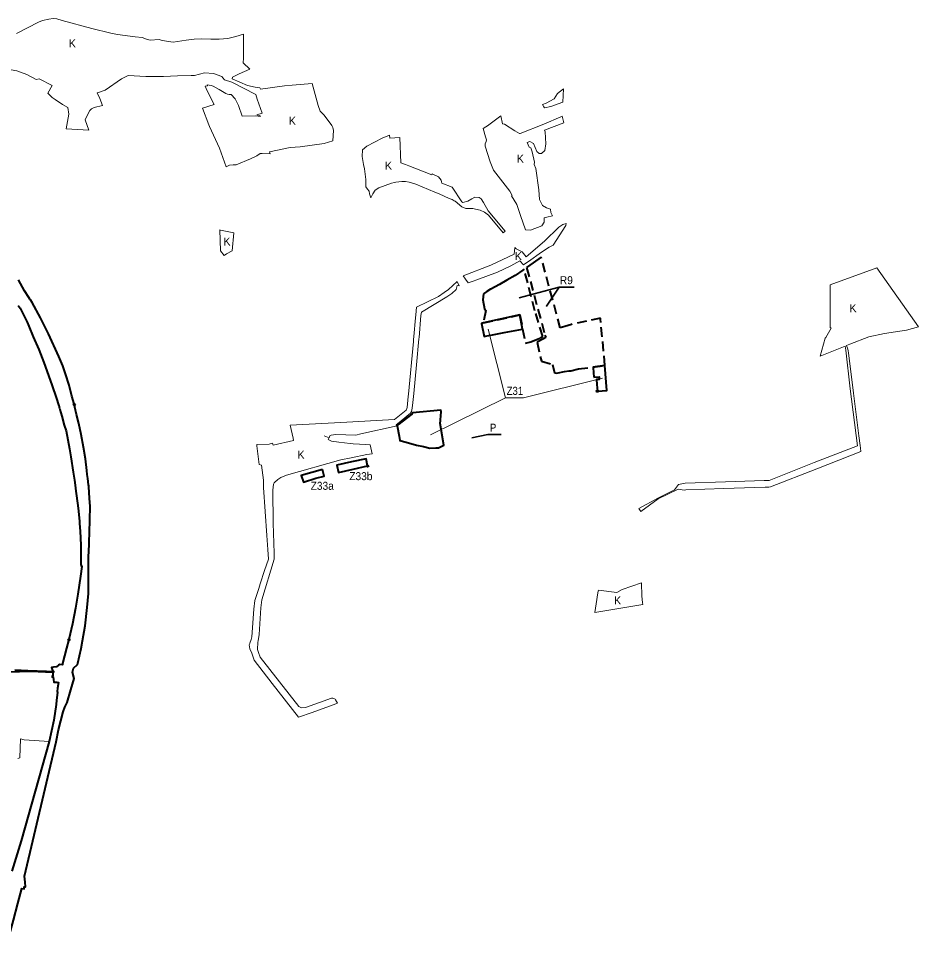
# Model space of a CAD drawing. Extents: x -650276 to -642489, y -1074311 to -1066658.
# Drawn here: x -645184 to -642489, y -1071606 to -1068813 of the extents above; entities that cross this region are included whole.
import ezdxf

# ---------------------------------------------------------------- set-up
doc = ezdxf.new("R2010")
doc.units = 0
doc.header["$LTSCALE"] = 9.6
doc.header["$PDMODE"] = 32
doc.header["$PDSIZE"] = 4.8
doc.linetypes.add('MEDIUM_DASHED', pattern=[4.5, 3, -1.5])
for name, color, linetype, lineweight in [('44', 7, 'Continuous', 40), ('45', 7, 'Continuous', 40), ('46', 7, 'Continuous', 13), ('47', 7, 'Continuous', 13), ('48', 7, 'Continuous', 13), ('60', 7, 'Continuous', 35), ('61', 7, 'MEDIUM_DASHED', 40), ('62', 7, 'Continuous', 35)]:
    doc.layers.add(name, color=color, linetype=linetype, lineweight=lineweight)

msp = doc.modelspace()

# ---------------------------------------------------------------- linework, layer by layer
at = {"layer": '44'}
for points in [[(-645017.46, -1069970.61), (-645018.28, -1069967.49), (-645024.45, -1069944.43), (-645032.85, -1069912.07), (-645043.5, -1069878.37), (-645051.78, -1069854.2), (-645063.26, -1069825.99), (-645095.1, -1069757.62), (-645118.98, -1069710.08), (-645143.56, -1069664.05), (-645148.8, -1069656.1), (-645150.3, -1069653.84), (-645153.33, -1069649.24), (-645166.67, -1069629), (-645184.88, -1069596.58)], [(-645185.17, -1069673.38), (-645179.12, -1069681.3), (-645170.3, -1069698.91), (-645158.43, -1069722.61), (-645153.44, -1069734.71), (-645140.27, -1069766.68), (-645123.84, -1069805.38), (-645108.74, -1069843.58), (-645094.42, -1069882.65), (-645083.31, -1069913.37), (-645071.53, -1069948.89), (-645063.96, -1069973.73), (-645063.23, -1069976.2), (-645062.57, -1069978.46), (-645061.76, -1069981.21), (-645060.612, -1069985.022), (-645054.73, -1070004.56), (-645047.28, -1070031.83), (-645042.27, -1070049.23), (-645032.21, -1070102.73), (-645027.49, -1070126.56), (-645021.14, -1070173.07), (-645018.56, -1070184.92), (-645016.92, -1070196.32), (-645013.77, -1070220.04), (-645013.51, -1070222.04), (-645005.98, -1070280.14), (-645002.308, -1070319.268), (-645001.81, -1070324.58), (-645001.64, -1070326.4)], [(-645010.54, -1069999.3), (-645015.548, -1069978.177), (-645016.01, -1069976.23), (-645016.89, -1069972.82), (-645017.46, -1069970.61)], [(-645166.34, -1071384.07), (-645071.99, -1070980.72), (-645064.39, -1070944.7), (-645050.47, -1070891.48), (-645045.74, -1070877.19), (-645043, -1070871.35), (-645039.25, -1070863.33), (-645028.25, -1070824.83), (-645018.18, -1070791.34), (-645023.25, -1070772.62), (-645019.57, -1070760.07), (-645007.68, -1070749.5), (-645006.739, -1070745.384), (-645001.71, -1070723.39), (-644997.14, -1070700.88), (-644992.6, -1070677.92), (-644985.04, -1070633.43), (-644978.44, -1070578.56), (-644975.05, -1070536.16), (-644974.44, -1070482.48), (-644975.29, -1070440.14), (-644974.69, -1070427.86), (-644972.48, -1070389.15), (-644971.37, -1070345.98), (-644970.61, -1070323.44), (-644970.55, -1070321.56), (-644970.524, -1070315.358), (-644970.36, -1070275.49), (-644971.47, -1070250.14), (-644974, -1070216.2), (-644974.29, -1070213.17), (-644974.49, -1070210.98), (-644976.94, -1070191.41), (-644978.49, -1070180.05), (-644979.57, -1070167.9), (-644984.21, -1070132.81), (-644989.62, -1070097.79), (-644996.88, -1070059.73), (-645004.02, -1070026.44), (-645010.54, -1069999.3)], [(-645001.64, -1070326.4), (-644999.47, -1070349.63), (-644997.87, -1070391.16), (-644998.25, -1070430.5), (-644998.17, -1070450.59), (-644995.14, -1070455.72), (-644998.92, -1070484.58), (-645006.44, -1070538.78), (-645014.07, -1070580.72), (-645022.64, -1070626.93), (-645033.53, -1070674.55)], [(-645033.53, -1070674.55), (-645041, -1070700.44), (-645046.63, -1070722.77), (-645052.4, -1070746.427), (-645053.21, -1070749.75), (-645060.46, -1070749.1), (-645065.17, -1070751.39), (-645070.3, -1070755.92), (-645079.38, -1070756.91), (-645085.58, -1070758.04), (-645081.6, -1070770.362)], [(-645195.527, -1070765.319), (-645156.988, -1070766.884), (-645100.32, -1070769.5), (-645081.6, -1070770.362), (-645081.75, -1070772.79), (-645125.217, -1070770.81), (-645143, -1070770), (-645161, -1070770), (-645182, -1070771), (-645303, -1070774)], [(-645081.6, -1070770.362), (-645081.75, -1070772.79), (-645081.85, -1070781.59), (-645081.57, -1070783.53), (-645083.95, -1070783.89), (-645083.49, -1070786.92), (-645081.13, -1070786.56), (-645078.85, -1070802.46), (-645070.2, -1070802.33), (-645065.01, -1070803.22), (-645068.07, -1070820.37)], [(-645068.07, -1070820.37), (-645068.52, -1070830.52), (-645068.07, -1070832.72), (-645071.18, -1070855.63), (-645071.77, -1070868.73), (-645078.23, -1070915.65)], [(-645078.23, -1070915.65), (-645092.67, -1070979.52), (-645176.14, -1071277.26), (-645204.341, -1071368.19)], [(-645222.48, -1071606.08), (-645211.27, -1071560.01), (-645199.61, -1071515.68), (-645186.67, -1071465.55), (-645175.06, -1071420.93), (-645167.58, -1071421.19), (-645167.37, -1071415.2), (-645163.56, -1071415.3), (-645164.76, -1071401.79), (-645166.34, -1071384.07)]]:
    msp.add_lwpolyline(points, dxfattribs=at)
for p in [(-645017.46, -1069970.61), (-645033.53, -1070674.55), (-645081.6, -1070770.362)]:
    msp.add_point(p, dxfattribs=at)
at = {"layer": '45'}
for p, q in [((-644138.78, -1070154.07), (-644143.31, -1070132.95)), ((-644182.31, -1070163.66), (-644138.78, -1070154.07))]:
    msp.add_line(p, q, dxfattribs=at)
for points in [[(-643791.88, -1069725.25), (-643797.75, -1069726.51), (-643789.3, -1069766.05), (-643786.35, -1069765.46), (-643764.94, -1069761.27), (-643729.34, -1069754.3), (-643674.3, -1069743.53), (-643682.61, -1069701.16)], [(-643791.88, -1069725.25), (-643797.75, -1069726.51), (-643789.3, -1069766.05), (-643786.35, -1069765.46), (-643764.94, -1069761.27), (-643729.34, -1069754.3), (-643674.3, -1069743.53), (-643682.61, -1069701.16)], [(-643920.84, -1070026.46), (-643920.29, -1070017.73), (-643920.16, -1070015.69), (-643918.69, -1069992.23), (-643918.88, -1069986.82), (-644004.06, -1069994.59), (-644005.92, -1069998.62), (-644044.7, -1070029.04), (-644050.12, -1070033.64), (-644044.18, -1070064.43), (-644041.71, -1070077.29), (-644022.77, -1070082.66), (-643991.99, -1070091.37), (-643971.03, -1070095.79), (-643951.99, -1070100.35), (-643933.96, -1070100.18), (-643926.33, -1070099.5), (-643909.87, -1070091.95)], [(-643920.84, -1070026.46), (-643920.29, -1070017.73), (-643920.16, -1070015.69), (-643918.69, -1069992.23), (-643918.88, -1069986.82), (-644004.06, -1069994.59), (-644005.92, -1069998.62), (-644044.7, -1070029.04), (-644050.12, -1070033.64), (-644044.18, -1070064.43), (-644041.71, -1070077.29), (-644022.77, -1070082.66), (-643991.99, -1070091.37), (-643971.03, -1070095.79), (-643951.99, -1070100.35), (-643933.96, -1070100.18), (-643926.33, -1070099.5), (-643909.87, -1070091.95)], [(-644274.246, -1070164.59), (-644337.256, -1070182.64), (-644331.096, -1070202.4), (-644294.206, -1070190.9), (-644269.036, -1070184.57)], [(-644274.246, -1070164.59), (-644337.256, -1070182.64), (-644331.096, -1070202.4), (-644294.206, -1070190.9), (-644269.036, -1070184.57)]]:
    msp.add_lwpolyline(points, close=True, dxfattribs=at)
for points in [[(-643450.3, -1069929.7), (-643422.204, -1069927.68), (-643427.6, -1069852.59), (-643463.51, -1069857.44)], [(-643463.51, -1069857.44), (-643463.31, -1069860.18), (-643461.327, -1069887.84)], [(-643461.327, -1069887.84), (-643445.37, -1069886.7), (-643444.79, -1069894.68), (-643452.77, -1069895.25), (-643451.74, -1069909.63), (-643450.3, -1069929.7)], [(-644143.31, -1070132.95), (-644143.31, -1070132.95), (-644143.31, -1070132.95), (-644187.11, -1070141.58), (-644230.4, -1070152.08), (-644226.23, -1070173.28), (-644182.31, -1070163.66)], [(-644143.31, -1070132.95), (-644143.31, -1070132.95), (-644143.31, -1070132.95), (-644187.11, -1070141.58), (-644230.4, -1070152.08), (-644226.23, -1070173.28), (-644182.31, -1070163.66)], [(-644182.31, -1070163.66), (-644138.78, -1070154.07), (-644143.31, -1070132.95)]]:
    msp.add_lwpolyline(points, dxfattribs=at)
for p in [(-643450.3, -1069929.7), (-644138.78, -1070154.07)]:
    msp.add_point(p, dxfattribs=at)
at = {"layer": '46'}
for points in [[(-643672.005, -1069949.473), (-643725.65, -1069949.473), (-643725.65, -1069949.473), (-643777.096, -1069744.435), (-643725.65, -1069949.473), (-643950.635, -1070061)], [(-643434.663, -1069891.167), (-643672.005, -1069949.473), (-643725.65, -1069949.473)]]:
    msp.add_lwpolyline(points, dxfattribs=at)
at = {"layer": '47'}
msp.add_line((-643785.6, -1069166.98), (-643782.92, -1069176.24), dxfattribs=at)
for points in [[(-645190.22, -1068857.23), (-645124.36, -1068824.11), (-645112.77, -1068819.13), (-645093.56, -1068814.27), (-645081.12, -1068813.15), (-645070.05, -1068814), (-645053.97, -1068818.31), (-644964.45, -1068842.38), (-644908.26, -1068856.91), (-644887.91, -1068860.82), (-644834.84, -1068867.4), (-644814.47, -1068870.12), (-644800.87, -1068874.97), (-644790.41, -1068877.73), (-644763.04, -1068875.63), (-644753.71, -1068878.41), (-644721.29, -1068883.2), (-644681.99, -1068878.15), (-644658.39, -1068874.59), (-644636.55, -1068874.02), (-644608.71, -1068874.78), (-644583.26, -1068874.26), (-644557.75, -1068872.33), (-644533.84, -1068867.2), (-644510.62, -1068859.35), (-644510.567, -1068897.909), (-644510.75, -1068931.16), (-644511.47, -1068945.37), (-644491.31, -1068964.35), (-644523.4, -1068978.98), (-644543.05, -1068988.64), (-644544.02, -1068993.75), (-644498.28, -1069013.19), (-644475.09, -1069018.99), (-644461.74, -1069020.83), (-644459.67, -1069024.41), (-644387.91, -1069014.64), (-644364.53, -1069012.83), (-644304.6, -1069007.55), (-644286.94, -1069073.19)], [(-645131.73, -1068995.69), (-645159.37, -1068981.11), (-645189.84, -1068969.91), (-645229.27, -1068962.28), (-645232.4, -1068961.67), (-645255.21, -1068962.49), (-645275.45, -1068964.38), (-645292.77, -1068966.91), (-645311.99, -1068972.74), (-645328.55, -1068980.37), (-645350.17, -1068993.33), (-645371.35, -1069010.64), (-645396.53, -1069030.88)], [(-644948.575, -1069035.675), (-644941.27, -1069052.9), (-644932.95, -1069073.65), (-644958.25, -1069079.99), (-644965.95, -1069083.67), (-644970.84, -1069088.8), (-644975.56, -1069097.564), (-644985.15, -1069116.67), (-644974.34, -1069147.85), (-645041.751, -1069143.816), (-645034.13, -1069099.79), (-645036.87, -1069079.78), (-645052.83, -1069070.4), (-645075.206, -1069055.523), (-645084.19, -1069049.55), (-645096.97, -1069036.63), (-645084.17, -1069013.922), (-645122.25, -1068993.21), (-645131.73, -1068995.69)], [(-644473.222, -1069040.994), (-644545.54, -1069003.12), (-644567.09, -1068996.26), (-644572.05, -1068991.08), (-644575.29, -1068986.48), (-644600.67, -1068977.77), (-644627.41, -1068975.6), (-644657.61, -1068983.91), (-644667.57, -1068983.47), (-644708.6, -1068984.54), (-644750.67, -1068986.34), (-644761.88, -1068986.27), (-644803.31, -1068986.97), (-644855.56, -1068983.38), (-644875.57, -1068993.47), (-644925.35, -1069027.75), (-644944.9, -1069035.04), (-644948.575, -1069035.675)], [(-644286.94, -1069073.19), (-644281.26, -1069090.19), (-644269.11, -1069102.31), (-644245.65, -1069133.66), (-644243.14, -1069139.47), (-644240.67, -1069148.58), (-644242.48, -1069179.49), (-644268.7, -1069187.42), (-644340.83, -1069197.13), (-644371.08, -1069199.84), (-644432.53, -1069212.02), (-644430.91, -1069218.82), (-644454.87, -1069217.05), (-644460.97, -1069217.61), (-644470.64, -1069224), (-644489.27, -1069233.04), (-644532.71, -1069251.12), (-644541.83, -1069251.66), (-644552.01, -1069252.24), (-644562.47, -1069257.56), (-644582.29, -1069201.27), (-644612.3, -1069136.45), (-644614.41, -1069131.08), (-644633.66, -1069082), (-644598.81, -1069071.02), (-644619.54, -1069029.55), (-644625.69, -1069015.84), (-644618.8, -1069014.7), (-644619.1, -1069011.81), (-644607.16, -1069013.56), (-644601.43, -1069015.74), (-644583.05, -1069025.29), (-644563.19, -1069037.21), (-644558.56, -1069039.86), (-644553.62, -1069040.53), (-644547.31, -1069040.11), (-644535.13, -1069053.18), (-644525.83, -1069073.84), (-644514.47, -1069105.62), (-644474.33, -1069104.22), (-644459.82, -1069106.73), (-644461.01, -1069104.36), (-644470.37, -1069101.55), (-644454.75, -1069096.51), (-644469.28, -1069054.8), (-644473.222, -1069040.994)], [(-643697.29, -1069149.7), (-643728.49, -1069129.95), (-643734.75, -1069128.3), (-643739.66, -1069104.58), (-643747.75, -1069110.71), (-643779.31, -1069134.63), (-643784.55, -1069137.77), (-643792.04, -1069142.27), (-643785.6, -1069166.98)], [(-643555.98, -1069105.57), (-643559.5, -1069107.98), (-643610.81, -1069129.04), (-643681.63, -1069157.04), (-643683.68, -1069157.86), (-643697.29, -1069149.7)], [(-643607.02, -1069152.34), (-643609.08, -1069147.64), (-643550.79, -1069125.24), (-643555.98, -1069105.57)], [(-643707.23, -1069344.52), (-643691.6, -1069370.3), (-643681.09, -1069403.24), (-643665.87, -1069446.1), (-643650.28, -1069446.91), (-643616.78, -1069433.81), (-643610.18, -1069422.91), (-643609.6, -1069409.99), (-643601.9, -1069408.43), (-643585.19, -1069404.76), (-643589.52, -1069393.88), (-643590.89, -1069383.9), (-643602.92, -1069380.53), (-643614.35, -1069373.28), (-643623.28, -1069355.47), (-643625.9, -1069326.77), (-643634.56, -1069262.02), (-643639.23, -1069250.38), (-643638.72, -1069242.94), (-643645.61, -1069212.25), (-643649.84, -1069200.4), (-643654.57, -1069198.77), (-643660.22, -1069184.11), (-643653.05, -1069180.98), (-643641.84, -1069187.68), (-643631.66, -1069211.67), (-643624.38, -1069217.27), (-643617.64, -1069217), (-643607.37, -1069208.43), (-643604.38, -1069188.48), (-643607.02, -1069152.34)], [(-644094.79, -1069171.27), (-644141.24, -1069195.17), (-644154.36, -1069206.06), (-644155.37, -1069226.72), (-644151.11, -1069250.7), (-644148.22, -1069263.22), (-644144.05, -1069295.67)], [(-644024.93, -1069250.23), (-644038.83, -1069245.65), (-644042.37, -1069169.77), (-644071.97, -1069171.72), (-644073.35, -1069162.84), (-644094.79, -1069171.27)], [(-643782.92, -1069176.24), (-643783.2, -1069181.85), (-643786.97, -1069188.11), (-643786.89, -1069195.02), (-643771.86, -1069242.77), (-643761.21, -1069267.12), (-643712.78, -1069330.24)], [(-643732.705, -1069454.79), (-643726.74, -1069450.72), (-643777.27, -1069389.71), (-643791.02, -1069364.54), (-643798.1, -1069353.51), (-643804.83, -1069348.99), (-643817.06, -1069348.14), (-643826.21, -1069352.92), (-643838.69, -1069360.79), (-643853.56, -1069364.44), (-643856.43, -1069362.68), (-643885.63, -1069318.72), (-643916.78, -1069305.89), (-643917.36, -1069302.04), (-643918.08, -1069297.33), (-643926.74, -1069287.37), (-643944.89, -1069278.32), (-643946.16, -1069281.84), (-644015.12, -1069254.24), (-644024.93, -1069250.23)], [(-644144.05, -1069295.67), (-644143.54, -1069317.05), (-644138.55, -1069324.23), (-644134.15, -1069330.45), (-644132.52, -1069338.02), (-644129.09, -1069349.83), (-644123.21, -1069338.41), (-644116.33, -1069327.36), (-644105.5, -1069320.03), (-644067.08, -1069306.15)], [(-644054.35, -1069303.55), (-644035.89, -1069301.02), (-644025.24, -1069301.38), (-644014.19, -1069303.36), (-643993.91, -1069309.57), (-643936.87, -1069332.93), (-643924.42, -1069338.29), (-643894.84, -1069352.76), (-643885.22, -1069355.58), (-643879.48, -1069359.13), (-643876.34, -1069360.61), (-643856.58, -1069377.59), (-643844.28, -1069382.26), (-643823.72, -1069382.61), (-643815.93, -1069384.23), (-643801.36, -1069387.23), (-643788.63, -1069393.7), (-643776.78, -1069401.87), (-643732.705, -1069454.79)], [(-644067.08, -1069306.15), (-644058.05, -1069304.02), (-644054.35, -1069303.55)], [(-643712.78, -1069330.24), (-643705.74, -1069343.54), (-643707.23, -1069344.52)], [(-643671.53, -1069551.1), (-643649.94, -1069535.93), (-643624.65, -1069517.85), (-643605.97, -1069505.47), (-643594.49, -1069498.17), (-643582.77, -1069491.76), (-643545.07, -1069432.89), (-643544.06, -1069427.6), (-643553.7, -1069430.44), (-643565.92, -1069438.4), (-643608.89, -1069479.72), (-643663.46, -1069526.87), (-643675.32, -1069512.62), (-643693.95, -1069503.38)], [(-643693.95, -1069503.38), (-643697.85, -1069499.21), (-643699.23, -1069519.48), (-643769.08, -1069551.96), (-643852.51, -1069584.08), (-643845.304, -1069594.087)], [(-643845.304, -1069594.087), (-643837.72, -1069604.62), (-643822.06, -1069600.07), (-643811.16, -1069596.45), (-643749.64, -1069573.35), (-643709.33, -1069554.14), (-643682.27, -1069539.41), (-643671.53, -1069551.1)], [(-642704.1, -1069793.095), (-642703.57, -1069792.88), (-642693.99, -1069788.85), (-642637.44, -1069766.81), (-642589.86, -1069757.1), (-642524.14, -1069746.8), (-642488.71, -1069736.85), (-642613.34, -1069559.68), (-642753.18, -1069610.65), (-642753.25, -1069738.59), (-642750.08, -1069740.57), (-642766.27, -1069769), (-642767.89, -1069771.42), (-642782.69, -1069824.93)], [(-644399.15, -1070188.55), (-644381.21, -1070181.71), (-644218.65, -1070135.75), (-644188.44, -1070129.43), (-644140.72, -1070119.57), (-644125, -1070117.83), (-644130.91, -1070091.1), (-644144.13, -1070089.47), (-644181.81, -1070087.51), (-644191.26, -1070086.47), (-644225.13, -1070082.95), (-644247.3, -1070079.69), (-644256.54, -1070075.02), (-644255.52, -1070072.5), (-644254.136, -1070069.079), (-644254.13, -1070069.08), (-644254.25, -1070069.37), (-644269.156, -1070063.55), (-644254.25, -1070069.37), (-644251.9, -1070063.55), (-644248.05, -1070061.33), (-644233.51, -1070059.54), (-644174.12, -1070062.16), (-644159.02, -1070057.84), (-644050.12, -1070033.64), (-644053.18, -1070030.57), (-644051.913, -1070029.549), (-644049.311, -1070027.453), (-644009.95, -1069995.74), (-644006.96, -1069990.34), (-644005.06, -1069981.28), (-644003.06, -1069964.06), (-644000.52, -1069937.19), (-643992.27, -1069851.31), (-643984.845, -1069772.863), (-643984.44, -1069768.58), (-643978.85, -1069703.4), (-643977.454, -1069692.683), (-643901.55, -1069646.92), (-643886.62, -1069636.87), (-643873.82, -1069625.05), (-643872.55, -1069620.75), (-643870.44, -1069613.56), (-643863.92, -1069613.9), (-643870.697, -1069601.241), (-643895.951, -1069625.069), (-643909.616, -1069634.267), (-643926.229, -1069646.367), (-643992.34, -1069677.76), (-643994.36, -1069701.05), (-643995.17, -1069710.42), (-643999.94, -1069765.62), (-644000.79, -1069775.42), (-644001.04, -1069778.063), (-644001.29, -1069780.7), (-644016.47, -1069938.99), (-644017.15, -1069945.93), (-644020.26, -1069978.38), (-644022.43, -1069984.87), (-644022.99, -1069986.58), (-644058.55, -1070014.4), (-644219.33, -1070023.53), (-644370.87, -1070032.13), (-644361.74, -1070070.32), (-644361.55, -1070070.345), (-644360.41, -1070077.91), (-644421.26, -1070091.99), (-644423.99, -1070086.17), (-644433.19, -1070088.37), (-644470.17, -1070089.43), (-644470.55, -1070093.61), (-644463.28, -1070149.42), (-644456.41, -1070151.18), (-644450.72, -1070196.97), (-644450.15, -1070219.06), (-644445.28, -1070290.84), (-644440.36, -1070362.62), (-644437.53, -1070404.1), (-644435.51, -1070433.85), (-644447.14, -1070467.28), (-644460.5, -1070507.68), (-644464.98, -1070521.13), (-644476.94, -1070557.45), (-644479.06, -1070583.13), (-644485.64, -1070666.7), (-644488.01, -1070674.2), (-644491.691, -1070685.524), (-644491.82, -1070685.92), (-644493.5, -1070689.75), (-644491.42, -1070702.64), (-644485.61, -1070714.95), (-644478.67, -1070736.28), (-644424.37, -1070806.03), (-644346.21, -1070906.61), (-644305.07, -1070893.39), (-644242.29, -1070869.82), (-644229.12, -1070865.52), (-644234.66, -1070855.08), (-644236.3, -1070852.87), (-644239.47, -1070850.71), (-644243.15, -1070849.89)], [(-642782.69, -1069824.93), (-642708.257, -1069794.779), (-642706.3, -1069806.69)], [(-642662.32, -1070100.64), (-642663.28, -1070092.67), (-642667.19, -1070063.71), (-642682.78, -1069935.98), (-642697.64, -1069815.14), (-642698.77, -1069809.17), (-642700.34, -1069804.12), (-642704.1, -1069793.095)], [(-642706.3, -1069806.69), (-642693.2, -1069922.89), (-642671.23, -1070094.16), (-642801.19, -1070143.75), (-642921.03, -1070191.32), (-642936.02, -1070197.23), (-642942.12, -1070197.4), (-642950.42, -1070197.58), (-643066.26, -1070201.69), (-643187.06, -1070205.98)], [(-642936.88, -1070217.27), (-642931.88, -1070217.1), (-642792.87, -1070162.36), (-642661.13, -1070110.48), (-642662.32, -1070100.64)], [(-644243.15, -1070849.89), (-644246.93, -1070850.52), (-644282.77, -1070863.19), (-644324.34, -1070877.71), (-644337.15, -1070878.64), (-644344.86, -1070875.09), (-644460.82, -1070727.21), (-644465.31, -1070713.25), (-644468.1, -1070704.23), (-644467.84, -1070682.37), (-644466.998, -1070678.065), (-644463.28, -1070659.06), (-644458.85, -1070579.04), (-644455.2, -1070554.88), (-644418.69, -1070433.36), (-644418.23, -1070415.62), (-644421.45, -1070325.29), (-644422.5, -1070226.42), (-644420.14, -1070208.56), (-644418.61, -1070204.51), (-644417.36, -1070203.24), (-644407.55, -1070194.16), (-644399.15, -1070188.55)], [(-643187.06, -1070205.98), (-643207.1, -1070209.72), (-643219.4, -1070225.8), (-643267.55, -1070249.49), (-643326.26, -1070281.43), (-643320, -1070290.2), (-643267.75, -1070252.77), (-643208.09, -1070223.14), (-643190.42, -1070226.99)], [(-643190.42, -1070226.99), (-643184.86, -1070225.91), (-643071.16, -1070221.95), (-642947.42, -1070217.64), (-642936.88, -1070217.27)], [(-643452.22, -1070592.35), (-643385.72, -1070580.86), (-643380.35, -1070580.14), (-643380.08, -1070580.09), (-643314.51, -1070569.69), (-643315.27, -1070563.2), (-643317.08, -1070544.75), (-643317.9, -1070504.73)], [(-643446.89, -1070526.01), (-643447.79, -1070528.63), (-643450.98, -1070547.74), (-643452.14, -1070554.77)], [(-643317.9, -1070504.73), (-643376.07, -1070524.59), (-643392.41, -1070533.68), (-643446.89, -1070526.01)], [(-643452.14, -1070554.77), (-643458.42, -1070593.43), (-643452.22, -1070592.35)], [(-645186.18, -1071030.83), (-645180.72, -1071028.86), (-645178.73, -1070972.35), (-645167.47, -1070975.2), (-645092.67, -1070979.52), (-645090.464, -1070969.761), (-645078.23, -1070915.65), (-645076.052, -1070899.832), (-645072.44, -1070873.596), (-645070.222, -1070848.57), (-645065.01, -1070803.22), (-645078.85, -1070802.46), (-645082.31, -1070770.329), (-645100.268, -1070771.946), (-645143, -1070770), (-645161, -1070770), (-645182, -1070771), (-645194.206, -1070771.303)]]:
    msp.add_lwpolyline(points, dxfattribs=at)
for points in [[(-643589.94, -1069076.36), (-643554.17, -1069063.59), (-643551.72, -1069023.19), (-643569.44, -1069037.24), (-643580.21, -1069053.96), (-643603.72, -1069066.5), (-643614.36, -1069070.29), (-643614.82, -1069070.45), (-643610.31, -1069077.52), (-643608.65, -1069080.11)], [(-644578.92, -1069446.8), (-644581.87, -1069446.28), (-644579.047, -1069509.608), (-644567.976, -1069522.752), (-644561.24, -1069518.27), (-644543.99, -1069508.88), (-644539, -1069454.88)]]:
    msp.add_lwpolyline(points, close=True, dxfattribs=at)
at = {"layer": '60'}
msp.add_lwpolyline([(-643738.691, -1070059.84), (-643778.124, -1070059.84), (-643826.476, -1070069.235)], dxfattribs=at)
msp.add_lwpolyline([(-643738.691, -1070059.84), (-643778.124, -1070059.84), (-643826.476, -1070069.235)], dxfattribs=at)
at = {"layer": '61'}
for points in [[(-643561.41, -1069740.406), (-643618.737, -1069528.647), (-643643.16, -1069545.42), (-643662.335, -1069558.944), (-643607.44, -1069761.72), (-643605.24, -1069768.92), (-643612.22, -1069772.9), (-643630.77, -1069783.44), (-643618, -1069840.01), (-643584.63, -1069849.66), (-643578.28, -1069874.97), (-643574.05, -1069875.85), (-643567.91, -1069874.7), (-643548.67, -1069871.08), (-643535.83, -1069869.23), (-643530.01, -1069869.17), (-643507.1, -1069863.33), (-643463.51, -1069857.44), (-643427.6, -1069852.59), (-643440.77, -1069713.85), (-643441.08, -1069710.59), (-643527.49, -1069729.78), (-643547.9, -1069735.62)], [(-643743.81, -1069610.19), (-643770.29, -1069624.14), (-643781.95, -1069630.63), (-643791.77, -1069637.88), (-643793.09, -1069656.07), (-643788.14, -1069682.71), (-643784.59, -1069688.47), (-643791.88, -1069725.25), (-643682.61, -1069701.16), (-643674.3, -1069743.53), (-643665.92, -1069785.96), (-643649.25, -1069782.43), (-643621.71, -1069770.11), (-643613.9, -1069765.6), (-643637.36, -1069688.73), (-643669.73, -1069564.16), (-643673.82, -1069567.04), (-643697, -1069582.64), (-643721.43, -1069596.72)]]:
    msp.add_lwpolyline(points, close=True, dxfattribs=at)
at = {"layer": '62'}
msp.add_lwpolyline([(-643519.721, -1069617.808), (-643564.914, -1069617.808), (-643602.876, -1069674.79), (-643564.914, -1069617.808), (-643685.127, -1069650.369)], dxfattribs=at)
at = {"layer": '62', "lineweight": 13}
msp.add_lwpolyline([(-643519.721, -1069617.808), (-643564.914, -1069617.808), (-643602.876, -1069674.79), (-643564.914, -1069617.808), (-643685.127, -1069650.369)], dxfattribs=at)

# ---------------------------------------------------------------- texts
at = {"layer": '46'}
for s, width, p in [('Z31', 0.9, (-643722.294, -1069940.847)), ('Z33b', 0.95, (-644193.607, -1070196.61)), ('Z33b', 0.95, (-644193.607, -1070196.61)), ('Z33a', 0.95, (-644309.424, -1070225.565)), ('Z33a', 0.95, (-644309.424, -1070225.565))]:
    msp.add_text(s, height=24, dxfattribs=dict(at, width=width)).set_placement(p)
at = {"layer": '48'}
for p in [(-645034.002, -1068899.33), (-644374.971, -1069131.317), (-644086.887, -1069265.894), (-643691.928, -1069244.995), (-644570.824, -1069493.226), (-644570.824, -1069493.226), (-643697.851, -1069536.996), (-642695.251, -1069693.065), (-644348.839, -1070132.426), (-643400.597, -1070568.968), (-643400.597, -1070568.968)]:
    msp.add_text('K', height=24, dxfattribs=at).set_placement(p)
at = {"layer": '60', "width": 0.9}
msp.add_text('P', height=24, dxfattribs=at).set_placement((-643772.431, -1070051.2))
msp.add_text('P', height=24, dxfattribs=at).set_placement((-643772.431, -1070051.2))
at = {"layer": '62', "width": 0.95}
msp.add_text('R9', height=24, dxfattribs=at).set_placement((-643562.88, -1069609.148))
msp.add_text('R9', height=24, dxfattribs=at).set_placement((-643562.88, -1069609.148))

doc.saveas('drawing.dxf')
